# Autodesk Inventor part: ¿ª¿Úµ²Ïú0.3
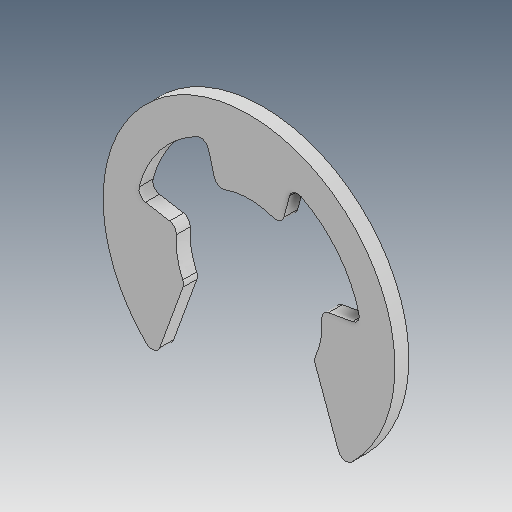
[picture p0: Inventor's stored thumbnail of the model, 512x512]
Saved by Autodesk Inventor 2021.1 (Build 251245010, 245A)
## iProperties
Created: 2015-08
Part Number: ¿ª¿Úµ²Ïú0.3
Material: Ogólny
Document SubType Name: Modeling
Designer: user
Density: 1 g/cm^3
Appearance: Domyślna
Author: user
Revision Number: ÈÎºÎ
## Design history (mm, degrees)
feature "Í¹Ì¨-À­Éì1"
node "Bryła1"
